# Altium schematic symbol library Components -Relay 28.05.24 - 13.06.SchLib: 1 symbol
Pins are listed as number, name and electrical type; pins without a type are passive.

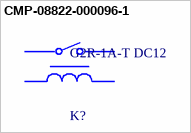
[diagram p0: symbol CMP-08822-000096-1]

## CMP-08822-000096-1
designator K?, comment G2R-1A-T DC12
RELAY GEN PURPOSE SPST 10A 12V; Operate Time: 15ms; Relay Type: General Purpose; Power Consumption: 530mW; Max Voltage Rating (AC): 380V; Approvals: UL; Coil Resistance: 275R; Coil Type: Non-Latching; Max Voltage Rating (DC): 125V; Coil Current: 43.6mA; Release Time: 5ms
footprint FP-G2R-1A-T_DC12-MFG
